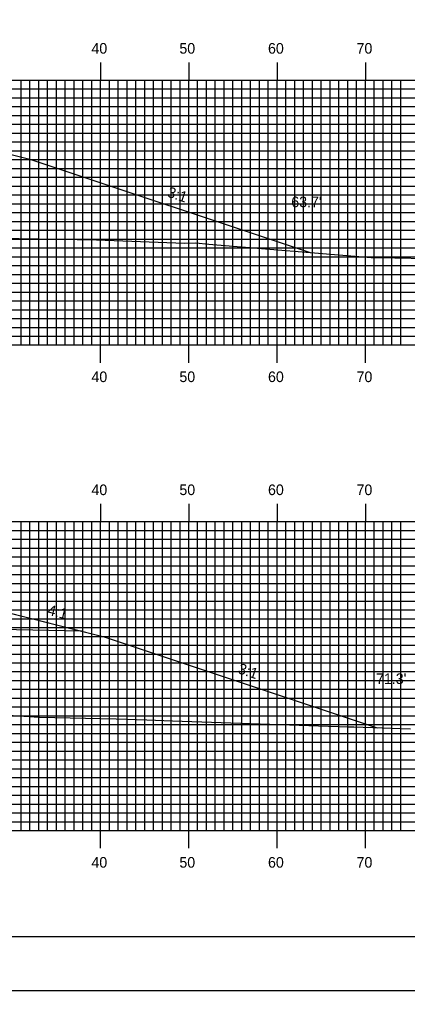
# Model space of a CAD drawing. Extents: x 1805864 to 1806208, y 442591 to 442811.
# Drawn here: x 1806061 to 1806105, y 442590.5 to 442700.5 of the extents above; entities that cross this region are included whole.
import ezdxf

# ---------------------------------------------------------------- set-up
doc = ezdxf.new("R2010")
doc.units = 0
for name, color, linetype in [('ANNOTATION', 7, 'Continuous'), ('BORDER', 7, 'Continuous'), ('D_Roadway_Centerline', 7, 'Continuous'), ('D_Roadway_SlopeLines', 7, 'Continuous'), ('D_Roadway_SubGrade', 7, 'Continuous'), ('D_Text_Standard', 7, 'Continuous'), ('H_V ANNOTATION', 7, 'Continuous'), ('MAJOR', 7, 'Continuous'), ('MINOR', 7, 'Continuous'), ('PLOT BOUNDARY', 7, 'Continuous'), ('S_Roadway_Centerline', 7, 'Continuous')]:
    doc.layers.add(name, color=color, linetype=linetype)

msp = doc.modelspace()

# ---------------------------------------------------------------- linework, layer by layer
at = {"layer": 'BORDER'}
msp.add_lwpolyline([(1805880.62, 442596.67), (1806200.62, 442596.67), (1806200.62, 442806.67), (1805880.62, 442806.67)], close=True, dxfattribs=at)
at = {"layer": 'D_Roadway_Centerline'}
for points in [[(1805981.53, 442679.08), (1805998.22, 442684.65), (1806000.05, 442685.1), (1806010.22, 442687.65), (1806018.22, 442687.97), (1806030.22, 442688.21), (1806042.22, 442688.05), (1806050.22, 442687.73), (1806060.39, 442685.19), (1806062.22, 442684.73), (1806093.95, 442674.16)], [(1805981.03, 442626.35), (1805998.22, 442630.65), (1806000.05, 442631.1), (1806010.22, 442633.65), (1806018.22, 442633.97), (1806030.22, 442634.21), (1806042.22, 442634.29), (1806058.63, 442633.63), (1806068.08, 442631.27), (1806070.63, 442630.63), (1806101.56, 442620.32)]]:
    msp.add_lwpolyline(points, dxfattribs=at)
at = {"layer": 'D_Roadway_SlopeLines'}
for points in [[(1806050.22, 442687.73), (1806062.22, 442684.73), (1806093.95, 442674.16)], [(1806058.63, 442633.63), (1806070.63, 442630.63), (1806101.56, 442620.32)]]:
    msp.add_lwpolyline(points, dxfattribs=at)
at = {"layer": 'D_Roadway_SubGrade'}
msp.add_lwpolyline([(1806018.22, 442631.47), (1806000.05, 442631.1), (1806010.22, 442633.65), (1806010.22, 442633.4), (1806018.22, 442633.72), (1806030.22, 442633.96), (1806042.22, 442634.04), (1806058.63, 442633.38), (1806058.63, 442633.63), (1806068.08, 442631.27), (1806042.22, 442631.79), (1806030.22, 442631.71)], close=True, dxfattribs=at)
at = {"layer": 'MAJOR'}
for p, q in [((1806070.22, 442695.67), (1806070.22, 442693.67)), ((1806080.22, 442695.67), (1806080.22, 442693.67)), ((1806090.22, 442695.67), (1806090.22, 442693.67)), ((1806100.22, 442695.67), (1806100.22, 442693.67)), ((1805890.22, 442693.67), (1806170.22, 442693.67)), ((1805890.22, 442693.67), (1806170.22, 442693.67)), ((1806070.22, 442663.67), (1806070.22, 442693.67)), ((1806080.22, 442663.67), (1806080.22, 442693.67)), ((1806090.22, 442663.67), (1806090.22, 442693.67)), ((1806100.22, 442663.67), (1806100.22, 442693.67)), ((1805890.22, 442688.67), (1806170.22, 442688.67)), ((1805890.22, 442683.67), (1806170.22, 442683.67)), ((1805890.22, 442678.67), (1806170.22, 442678.67)), ((1805890.22, 442673.67), (1806170.22, 442673.67)), ((1805890.22, 442668.67), (1806170.22, 442668.67)), ((1805890.22, 442663.67), (1806170.22, 442663.67)), ((1805890.22, 442663.67), (1806170.22, 442663.67)), ((1806070.22, 442661.66), (1806070.22, 442663.67)), ((1806080.22, 442661.66), (1806080.22, 442663.67)), ((1806090.22, 442661.66), (1806090.22, 442663.67)), ((1806100.22, 442661.66), (1806100.22, 442663.67)), ((1806070.22, 442645.67), (1806070.22, 442643.67)), ((1806080.22, 442645.67), (1806080.22, 442643.67)), ((1806090.22, 442645.67), (1806090.22, 442643.67)), ((1806100.22, 442645.67), (1806100.22, 442643.67)), ((1805890.22, 442643.67), (1806170.22, 442643.67)), ((1805890.22, 442643.67), (1806170.22, 442643.67)), ((1806070.22, 442608.67), (1806070.22, 442643.67)), ((1806080.22, 442608.67), (1806080.22, 442643.67)), ((1806090.22, 442608.67), (1806090.22, 442643.67)), ((1806100.22, 442608.67), (1806100.22, 442643.67)), ((1805890.22, 442638.67), (1806170.22, 442638.67)), ((1805890.22, 442633.67), (1806170.22, 442633.67)), ((1805890.22, 442628.67), (1806170.22, 442628.67)), ((1805890.22, 442623.67), (1806170.22, 442623.67)), ((1805890.22, 442618.67), (1806170.22, 442618.67)), ((1805890.22, 442613.67), (1806170.22, 442613.67)), ((1805890.22, 442608.67), (1806170.22, 442608.67)), ((1805890.22, 442608.67), (1806170.22, 442608.67)), ((1806070.22, 442606.66), (1806070.22, 442608.67)), ((1806080.22, 442606.66), (1806080.22, 442608.67)), ((1806090.22, 442606.66), (1806090.22, 442608.67)), ((1806100.22, 442606.66), (1806100.22, 442608.67))]:
    msp.add_line(p, q, dxfattribs=at)
at = {"layer": 'MINOR'}
for p, q in [((1806061.22, 442663.67), (1806061.22, 442693.67)), ((1806062.22, 442663.67), (1806062.22, 442693.67)), ((1806063.22, 442663.67), (1806063.22, 442693.67)), ((1806064.22, 442663.67), (1806064.22, 442693.67)), ((1806065.22, 442663.67), (1806065.22, 442693.67)), ((1806066.22, 442663.67), (1806066.22, 442693.67)), ((1806067.22, 442663.67), (1806067.22, 442693.67)), ((1806068.22, 442663.67), (1806068.22, 442693.67)), ((1806069.22, 442663.67), (1806069.22, 442693.67)), ((1806071.22, 442663.67), (1806071.22, 442693.67)), ((1806072.22, 442663.67), (1806072.22, 442693.67)), ((1806073.22, 442663.67), (1806073.22, 442693.67)), ((1806074.22, 442663.67), (1806074.22, 442693.67)), ((1806075.22, 442663.67), (1806075.22, 442693.67)), ((1806076.22, 442663.67), (1806076.22, 442693.67)), ((1806077.22, 442663.67), (1806077.22, 442693.67)), ((1806078.22, 442663.67), (1806078.22, 442693.67)), ((1806079.22, 442663.67), (1806079.22, 442693.67)), ((1806081.22, 442663.67), (1806081.22, 442693.67)), ((1806082.22, 442663.67), (1806082.22, 442693.67)), ((1806083.22, 442663.67), (1806083.22, 442693.67)), ((1806084.22, 442663.67), (1806084.22, 442693.67)), ((1806085.22, 442663.67), (1806085.22, 442693.67)), ((1806086.22, 442663.67), (1806086.22, 442693.67)), ((1806087.22, 442663.67), (1806087.22, 442693.67)), ((1806088.22, 442663.67), (1806088.22, 442693.67)), ((1806089.22, 442663.67), (1806089.22, 442693.67)), ((1806091.22, 442663.67), (1806091.22, 442693.67)), ((1806092.22, 442663.67), (1806092.22, 442693.67)), ((1806093.22, 442663.67), (1806093.22, 442693.67)), ((1806094.22, 442663.67), (1806094.22, 442693.67)), ((1806095.22, 442663.67), (1806095.22, 442693.67)), ((1806096.22, 442663.67), (1806096.22, 442693.67)), ((1806097.22, 442663.67), (1806097.22, 442693.67)), ((1806098.22, 442663.67), (1806098.22, 442693.67)), ((1806099.22, 442663.67), (1806099.22, 442693.67)), ((1806101.22, 442663.67), (1806101.22, 442693.67)), ((1806102.22, 442663.67), (1806102.22, 442693.67)), ((1806103.22, 442663.67), (1806103.22, 442693.67)), ((1806104.22, 442663.67), (1806104.22, 442693.67)), ((1805890.22, 442692.67), (1806170.22, 442692.67)), ((1805890.22, 442691.67), (1806170.22, 442691.67)), ((1805890.22, 442690.67), (1806170.22, 442690.67)), ((1805890.22, 442689.67), (1806170.22, 442689.67)), ((1805890.22, 442687.67), (1806170.22, 442687.67)), ((1805890.22, 442686.67), (1806170.22, 442686.67)), ((1805890.22, 442685.67), (1806170.22, 442685.67)), ((1805890.22, 442684.67), (1806170.22, 442684.67)), ((1805890.22, 442682.67), (1806170.22, 442682.67)), ((1805890.22, 442681.67), (1806170.22, 442681.67)), ((1805890.22, 442680.67), (1806170.22, 442680.67)), ((1805890.22, 442679.67), (1806170.22, 442679.67)), ((1805890.22, 442677.67), (1806170.22, 442677.67)), ((1805890.22, 442676.67), (1806170.22, 442676.67)), ((1805890.22, 442675.67), (1806170.22, 442675.67)), ((1805890.22, 442674.67), (1806170.22, 442674.67)), ((1805890.22, 442672.67), (1806170.22, 442672.67)), ((1805890.22, 442671.67), (1806170.22, 442671.67)), ((1805890.22, 442670.67), (1806170.22, 442670.67)), ((1805890.22, 442669.67), (1806170.22, 442669.67)), ((1805890.22, 442667.67), (1806170.22, 442667.67)), ((1805890.22, 442666.67), (1806170.22, 442666.67)), ((1805890.22, 442665.67), (1806170.22, 442665.67)), ((1805890.22, 442664.67), (1806170.22, 442664.67)), ((1806061.22, 442608.67), (1806061.22, 442643.67)), ((1806062.22, 442608.67), (1806062.22, 442643.67)), ((1806063.22, 442608.67), (1806063.22, 442643.67)), ((1806064.22, 442608.67), (1806064.22, 442643.67)), ((1806065.22, 442608.67), (1806065.22, 442643.67)), ((1806066.22, 442608.67), (1806066.22, 442643.67)), ((1806067.22, 442608.67), (1806067.22, 442643.67)), ((1806068.22, 442608.67), (1806068.22, 442643.67)), ((1806069.22, 442608.67), (1806069.22, 442643.67)), ((1806071.22, 442608.67), (1806071.22, 442643.67)), ((1806072.22, 442608.67), (1806072.22, 442643.67)), ((1806073.22, 442608.67), (1806073.22, 442643.67)), ((1806074.22, 442608.67), (1806074.22, 442643.67)), ((1806075.22, 442608.67), (1806075.22, 442643.67)), ((1806076.22, 442608.67), (1806076.22, 442643.67)), ((1806077.22, 442608.67), (1806077.22, 442643.67)), ((1806078.22, 442608.67), (1806078.22, 442643.67)), ((1806079.22, 442608.67), (1806079.22, 442643.67)), ((1806081.22, 442608.67), (1806081.22, 442643.67)), ((1806082.22, 442608.67), (1806082.22, 442643.67)), ((1806083.22, 442608.67), (1806083.22, 442643.67)), ((1806084.22, 442608.67), (1806084.22, 442643.67)), ((1806085.22, 442608.67), (1806085.22, 442643.67)), ((1806086.22, 442608.67), (1806086.22, 442643.67)), ((1806087.22, 442608.67), (1806087.22, 442643.67)), ((1806088.22, 442608.67), (1806088.22, 442643.67)), ((1806089.22, 442608.67), (1806089.22, 442643.67)), ((1806091.22, 442608.67), (1806091.22, 442643.67)), ((1806092.22, 442608.67), (1806092.22, 442643.67)), ((1806093.22, 442608.67), (1806093.22, 442643.67)), ((1806094.22, 442608.67), (1806094.22, 442643.67)), ((1806095.22, 442608.67), (1806095.22, 442643.67)), ((1806096.22, 442608.67), (1806096.22, 442643.67)), ((1806097.22, 442608.67), (1806097.22, 442643.67)), ((1806098.22, 442608.67), (1806098.22, 442643.67)), ((1806099.22, 442608.67), (1806099.22, 442643.67)), ((1806101.22, 442608.67), (1806101.22, 442643.67)), ((1806102.22, 442608.67), (1806102.22, 442643.67)), ((1806103.22, 442608.67), (1806103.22, 442643.67)), ((1806104.22, 442608.67), (1806104.22, 442643.67)), ((1805890.22, 442642.67), (1806170.22, 442642.67)), ((1805890.22, 442641.67), (1806170.22, 442641.67)), ((1805890.22, 442640.67), (1806170.22, 442640.67)), ((1805890.22, 442639.67), (1806170.22, 442639.67)), ((1805890.22, 442637.67), (1806170.22, 442637.67)), ((1805890.22, 442636.67), (1806170.22, 442636.67)), ((1805890.22, 442635.67), (1806170.22, 442635.67)), ((1805890.22, 442634.67), (1806170.22, 442634.67)), ((1805890.22, 442632.67), (1806170.22, 442632.67)), ((1805890.22, 442631.67), (1806170.22, 442631.67)), ((1805890.22, 442630.67), (1806170.22, 442630.67)), ((1805890.22, 442629.67), (1806170.22, 442629.67)), ((1805890.22, 442627.67), (1806170.22, 442627.67)), ((1805890.22, 442626.67), (1806170.22, 442626.67)), ((1805890.22, 442625.67), (1806170.22, 442625.67)), ((1805890.22, 442624.67), (1806170.22, 442624.67)), ((1805890.22, 442622.67), (1806170.22, 442622.67)), ((1805890.22, 442621.67), (1806170.22, 442621.67)), ((1805890.22, 442620.67), (1806170.22, 442620.67)), ((1805890.22, 442619.67), (1806170.22, 442619.67)), ((1805890.22, 442617.67), (1806170.22, 442617.67)), ((1805890.22, 442616.67), (1806170.22, 442616.67)), ((1805890.22, 442615.67), (1806170.22, 442615.67)), ((1805890.22, 442614.67), (1806170.22, 442614.67)), ((1805890.22, 442612.67), (1806170.22, 442612.67)), ((1805890.22, 442611.67), (1806170.22, 442611.67)), ((1805890.22, 442610.67), (1806170.22, 442610.67)), ((1805890.22, 442609.67), (1806170.22, 442609.67))]:
    msp.add_line(p, q, dxfattribs=at)
at = {"layer": 'PLOT BOUNDARY'}
msp.add_lwpolyline([(1805864.43, 442590.55), (1806204.43, 442590.55), (1806204.43, 442810.55), (1805864.43, 442810.55)], close=True, dxfattribs=at)
at = {"layer": 'S_Roadway_Centerline'}
for points in [[(1805978.48, 442679.38), (1805999.99, 442677.25), (1806004.2, 442677.05), (1806016.96, 442676.28), (1806022.76, 442676.11), (1806029.55, 442676.04), (1806045.73, 442675.68), (1806055.84, 442675.85), (1806058.78, 442675.76), (1806069.77, 442675.59), (1806079.73, 442675.22), (1806081.03, 442675.24), (1806082.49, 442675.09), (1806100.88, 442673.59), (1806103.55, 442673.53), (1806107.22, 442673.47), (1806120.27, 442673.26), (1806132.04, 442673.29), (1806136.93, 442673.2), (1806141.24, 442673.03), (1806145.01, 442672.98), (1806163.14, 442672.64), (1806166.03, 442672.6), (1806170.22, 442672.45)], [(1805968.82, 442627.07), (1805982.88, 442626.24), (1805993.89, 442626.2), (1806001.27, 442625.65), (1806014.68, 442624.61), (1806016.68, 442624.4), (1806019.54, 442624.36), (1806028.84, 442624.06), (1806036.34, 442623.39), (1806040.68, 442622.84), (1806045.49, 442622.63), (1806063.3, 442621.52), (1806072, 442621.34), (1806075.48, 442621.21), (1806078.38, 442621.11), (1806098.23, 442620.43), (1806098.57, 442620.41), (1806098.9, 442620.42), (1806105.34, 442620.19)]]:
    msp.add_lwpolyline(points, dxfattribs=at)

# ---------------------------------------------------------------- texts
at = {"layer": 'ANNOTATION'}
for s, rotation, p in [('3:1', 341.5652, (1806077.69, 442680.49)), ('4:1', 345.9638, (1806064.14, 442633.12)), ('3:1', 341.5652, (1806085.7, 442626.52))]:
    msp.add_text(s, height=1.2, rotation=rotation, dxfattribs=at).set_placement(p)
at = {"layer": 'D_Text_Standard'}
for s, p in [("63.7'", (1806091.83, 442679.28)), ("71.3'", (1806101.43, 442625.27))]:
    msp.add_text(s, height=1.2, dxfattribs=at).set_placement(p)
at = {"layer": 'H_V ANNOTATION'}
for s, p in [('40', (1806069.19, 442696.67)), ('50', (1806079.15, 442696.67)), ('60', (1806089.19, 442696.67)), ('70', (1806099.22, 442696.67)), ('40', (1806069.19, 442659.47)), ('50', (1806079.15, 442659.47)), ('60', (1806089.19, 442659.47)), ('70', (1806099.22, 442659.47)), ('40', (1806069.19, 442646.67)), ('50', (1806079.15, 442646.67)), ('60', (1806089.19, 442646.67)), ('70', (1806099.22, 442646.67)), ('40', (1806069.19, 442604.47)), ('50', (1806079.15, 442604.47)), ('60', (1806089.19, 442604.47)), ('70', (1806099.22, 442604.47))]:
    msp.add_text(s, height=1.2, dxfattribs=at).set_placement(p)

doc.saveas('drawing.dxf')
